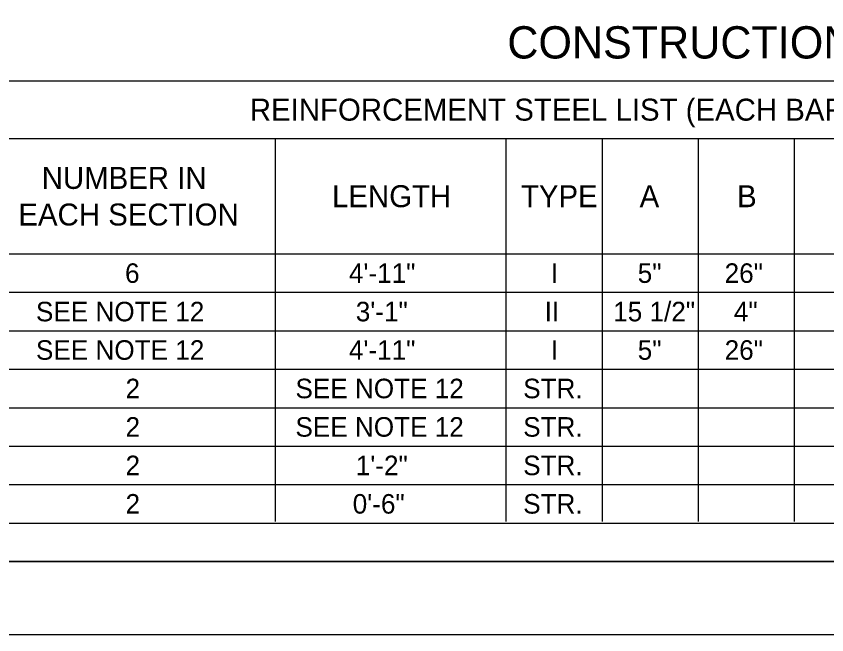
# Model space of a CAD drawing. Extents: x 499883 to 500983, y 499104 to 499764.
# Drawn here: x 500228.2 to 500394.2, y 499103.6 to 499230.3 of the extents above; entities that cross this region are included whole.
import ezdxf

# ---------------------------------------------------------------- set-up
doc = ezdxf.new("R2010")
doc.units = 0
for name, color, linetype in [('1', 7, 'Continuous'), ('41', 7, 'Continuous'), ('5', 7, 'Continuous')]:
    doc.layers.add(name, color=color, linetype=linetype)

msp = doc.modelspace()

# ---------------------------------------------------------------- linework, layer by layer
at = {"layer": '1'}
for p, q in [((499989.94, 499118.64), (500979.94, 499118.64)), ((500982.94, 499103.64), (499934.77, 499103.64))]:
    msp.add_line(p, q, dxfattribs=at)
at = {"layer": '41'}
for points in [[(499934.77, 499763.64), (500982.94, 499763.64), (500982.94, 499103.64), (499934.77, 499103.64)], [(499989.94, 499748.64), (500979.94, 499748.64), (500979.94, 499118.64), (499989.94, 499118.64)]]:
    msp.add_lwpolyline(points, close=True, dxfattribs=at)
at = {"layer": '5'}
for p, q in [((500174.98, 499217.06), (500545.06, 499217.06)), ((500174.98, 499205.25), (500545.06, 499205.25)), ((500281.28, 499205.25), (500281.28, 499126.84)), ((500328.52, 499205.25), (500328.52, 499126.84)), ((500348.21, 499205.25), (500348.21, 499126.84)), ((500367.89, 499205.25), (500367.89, 499126.84)), ((500387.58, 499205.25), (500387.58, 499126.84)), ((500174.98, 499181.63), (500545.06, 499181.63)), ((500174.98, 499173.76), (500545.06, 499173.76)), ((500174.98, 499165.88), (500545.06, 499165.88)), ((500174.98, 499158.01), (500545.06, 499158.01)), ((500174.98, 499150.13), (500545.06, 499150.13)), ((500174.98, 499142.26), (500545.06, 499142.26)), ((500174.98, 499134.39), (500545.06, 499134.39)), ((500174.98, 499126.51), (500545.06, 499126.51))]:
    msp.add_line(p, q, dxfattribs=at)

# ---------------------------------------------------------------- texts
for s, height, p in [('CONSTRUCTION BARRIER CURB', 6.6001, (500328.8, 499221.64)), ('REINFORCEMENT STEEL LIST (EACH BARRIER SECTION)', 4.5, (500276.06, 499208.91)), ('NUMBER IN', 4.5, (500233.43, 499194.94)), ('LENGTH', 4.5, (500292.9, 499191.19)), ('TYPE', 4.5, (500331.59, 499191.19)), ('A', 4.5, (500355.9, 499191.19)), ('B', 4.5, (500375.86, 499191.19)), ('EACH SECTION', 4.5, (500228.65, 499187.44)), ('6', 4, (500250.5, 499175.69)), ('4\'-11"', 4, (500296.35, 499175.69)), ('I', 4, (500337.74, 499175.69)), ('5"', 4, (500355.51, 499175.69)), ('26"', 4, (500373.31, 499175.69)), ('SEE NOTE 12', 4, (500232.25, 499167.82)), ('3\'-1"', 4, (500297.76, 499167.82)), ('II', 4, (500336.45, 499167.82)), ('15 1/2"', 4, (500350.49, 499167.82)), ('4"', 4, (500375.2, 499167.82)), ('SEE NOTE 12', 4, (500232.25, 499159.95)), ('4\'-11"', 4, (500296.35, 499159.95)), ('I', 4, (500337.74, 499159.95)), ('5"', 4, (500355.51, 499159.95)), ('26"', 4, (500373.31, 499159.95)), ('2', 4, (500250.61, 499152.07)), ('SEE NOTE 12', 4, (500285.4, 499152.07)), ('STR.', 4, (500332.05, 499152.07)), ('2', 4, (500250.61, 499144.2)), ('SEE NOTE 12', 4, (500285.4, 499144.2)), ('STR.', 4, (500332.05, 499144.2)), ('2', 4, (500250.61, 499136.32)), ('1\'-2"', 4, (500297.76, 499136.32)), ('STR.', 4, (500332.05, 499136.32)), ('2', 4, (500250.61, 499128.45)), ('0\'-6"', 4, (500297.13, 499128.45)), ('STR.', 4, (500332.05, 499128.45))]:
    msp.add_text(s, height=height, dxfattribs=at).set_placement(p)

doc.saveas('drawing.dxf')
